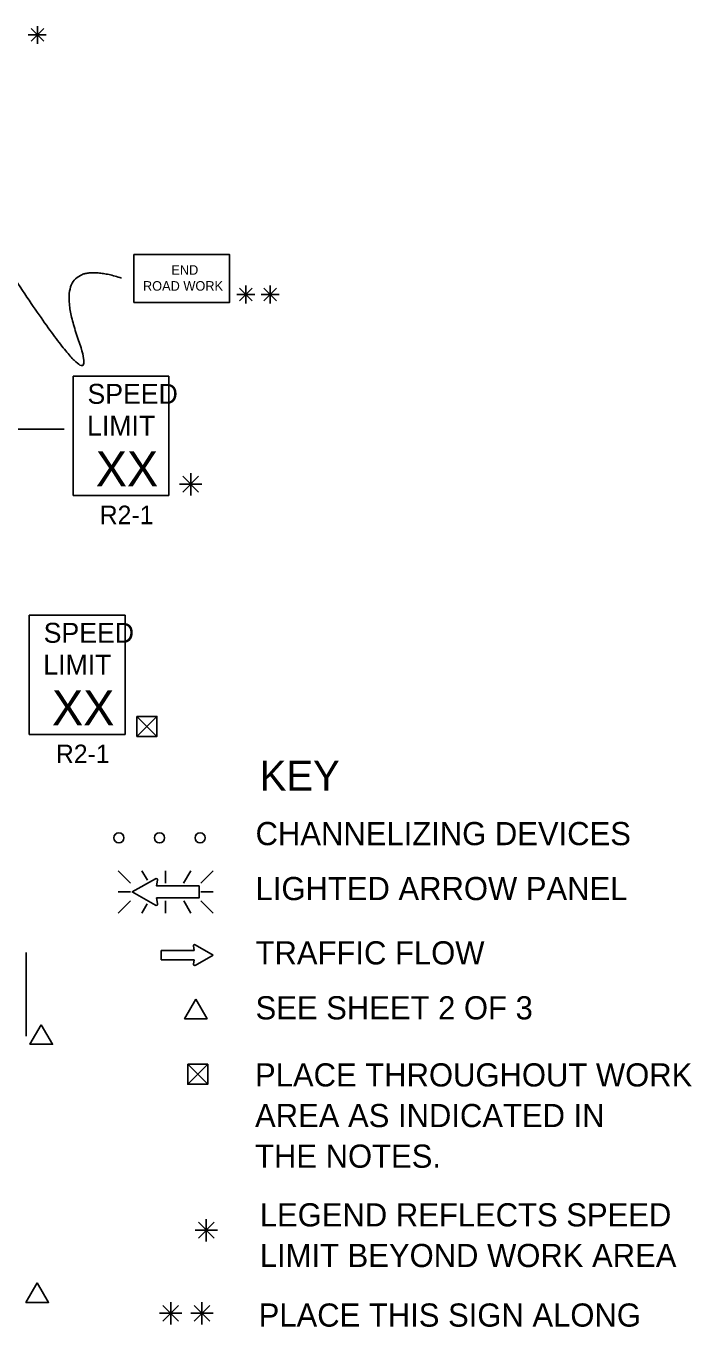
# Model space of a CAD drawing. Extents: x 16486 to 19505, y 5576 to 6998.
# Drawn here: x 17161 to 17428, y 6304 to 6826 of the extents above; entities that cross this region are included whole.
import ezdxf

# ---------------------------------------------------------------- set-up
doc = ezdxf.new("R2010")
doc.units = 0
for name, color, linetype in [('MT_SCRATCH_LEVEL_E', 7, 'Continuous'), ('TRAFFIC_SIGNS_PR', 7, 'Continuous'), ('TYPICAL_TEXT_DIMEN_EX', 7, 'Continuous'), ('TYPICAL_TEXT_DIMEN_PR', 7, 'Continuous')]:
    doc.layers.add(name, color=color, linetype=linetype)

msp = doc.modelspace()

# ---------------------------------------------------------------- linework, layer by layer
at = {"layer": 'MT_SCRATCH_LEVEL_E'}
for p, q in [((17227.72, 6457.25), (17228.03, 6455.48)), ((17235.64, 6453.62), (17228.4, 6457.73)), ((17228.03, 6455.48), (17214.78, 6455.48)), ((17214.78, 6455.48), (17214.78, 6451.73)), ((17228.4, 6449.48), (17235.64, 6453.62)), ((17214.78, 6451.73), (17228.03, 6451.73)), ((17228.03, 6451.73), (17227.72, 6449.95))]:
    msp.add_line(p, q, dxfattribs=at)
for centre, start, end in [((17228.18, 6457.33), 60.4248, 189.9638), ((17228.18, 6449.89), 170.0362, 299.7731)]:
    msp.add_arc(centre, 0.463, start, end, dxfattribs=at)
at = {"layer": 'TRAFFIC_SIGNS_PR'}
for p, q in [((17179.45, 6685.93), (17217.85, 6685.93)), ((17179.45, 6637.93), (17179.45, 6685.93)), ((17217.85, 6637.93), (17217.85, 6685.93)), ((17179.45, 6637.93), (17217.85, 6637.93)), ((17161.88, 6590.04), (17200.28, 6590.04)), ((17161.88, 6542.04), (17161.88, 6590.04)), ((17200.28, 6542.04), (17200.28, 6590.04)), ((17161.88, 6542.04), (17200.28, 6542.04)), ((17197.49, 6487.43), (17202.43, 6482.5)), ((17209.26, 6483.61), (17207.05, 6487.44)), ((17216.58, 6482.5), (17216.58, 6487.44)), ((17223.81, 6482.5), (17226.66, 6487.44)), ((17230.72, 6482.5), (17235.66, 6487.44)), ((17202.43, 6478.94), (17197.49, 6478.94)), ((17230.72, 6478.94), (17235.66, 6478.94)), ((17197.49, 6470.46), (17202.43, 6475.39)), ((17207, 6470.45), (17209.12, 6474.12)), ((17216.58, 6475.39), (17216.58, 6470.45)), ((17226.7, 6470.45), (17223.85, 6475.39)), ((17230.72, 6475.39), (17235.66, 6470.45)), ((17160.55, 6454.67), (17160.55, 6421.07))]:
    msp.add_line(p, q, dxfattribs=at)
msp.add_lwpolyline([(17203.87, 6715.44), (17242.27, 6715.44), (17242.27, 6734.64), (17203.87, 6734.64)], close=True, dxfattribs=at)
for points in [[(17212.5, 6484.22), (17203.21, 6478.94), (17212.51, 6473.62)], [(17213.38, 6474.25), (17212.98, 6476.52), (17229.99, 6476.52), (17229.99, 6481.32), (17212.98, 6481.32), (17213.38, 6483.6)]]:
    msp.add_lwpolyline(points, dxfattribs=at)
for centre in [(17197.83, 6500.63), (17214.13, 6500.63), (17230.43, 6500.63)]:
    msp.add_circle(centre, 2, dxfattribs=at)
for centre, radius, start, end in [((17212.79, 6483.7), 0.598, 350.7308, 118.8916), ((17212.79, 6474.15), 0.597, 241.4833, 9.9593)]:
    msp.add_arc(centre, radius, start, end, dxfattribs=at)
at = {"layer": 'TYPICAL_TEXT_DIMEN_PR'}
for p, q in [((17165.11, 6822.8), (17161.48, 6822.8)), ((17162.56, 6825.36), (17167.66, 6820.25)), ((17167.66, 6825.36), (17162.56, 6820.25)), ((17165.11, 6822.8), (17165.11, 6826.37)), ((17165.11, 6822.8), (17167.66, 6822.8)), ((17165.11, 6822.8), (17168.69, 6822.8)), ((17165.11, 6822.8), (17165.11, 6819.2)), ((17248.82, 6718.65), (17245.19, 6718.65)), ((17246.27, 6721.2), (17251.37, 6716.1)), ((17251.37, 6721.2), (17246.27, 6716.1)), ((17248.82, 6718.65), (17248.82, 6722.21)), ((17248.82, 6718.65), (17251.37, 6718.65)), ((17248.82, 6718.65), (17252.4, 6718.65)), ((17248.82, 6718.65), (17248.82, 6715.05)), ((17258.57, 6718.65), (17254.94, 6718.65)), ((17261.12, 6721.2), (17256.01, 6716.1)), ((17256.02, 6721.2), (17261.12, 6716.1)), ((17258.57, 6718.65), (17258.57, 6722.21)), ((17258.57, 6718.65), (17261.12, 6718.65)), ((17258.57, 6718.65), (17262.15, 6718.65)), ((17258.57, 6718.65), (17258.57, 6715.05)), ((17142.7, 6664.64), (17175.9, 6664.64)), ((17142.7, 6664.64), (17175.9, 6664.64)), ((17142.7, 6664.64), (17175.9, 6664.64)), ((17223.45, 6645.73), (17229.83, 6639.36)), ((17229.83, 6645.73), (17223.45, 6639.36)), ((17226.64, 6642.55), (17226.64, 6647)), ((17226.64, 6642.55), (17222.11, 6642.55)), ((17226.64, 6642.55), (17229.83, 6642.55)), ((17226.64, 6642.55), (17231.12, 6642.55)), ((17226.64, 6642.55), (17226.64, 6638.05)), ((17205.07, 6549.36), (17213.07, 6541.36)), ((17205.07, 6541.36), (17213.07, 6549.36)), ((17225.49, 6409.76), (17233.49, 6401.76)), ((17225.49, 6401.76), (17233.49, 6409.76)), ((17232.92, 6343.19), (17232.92, 6347.64)), ((17232.92, 6343.19), (17228.38, 6343.19)), ((17229.73, 6346.37), (17236.1, 6340)), ((17236.1, 6346.37), (17229.73, 6340)), ((17232.92, 6343.19), (17236.1, 6343.19)), ((17232.92, 6343.19), (17237.39, 6343.19)), ((17232.92, 6343.19), (17232.92, 6338.69)), ((17215.44, 6313.03), (17221.81, 6306.66)), ((17221.81, 6313.03), (17215.44, 6306.66)), ((17218.63, 6309.85), (17218.63, 6314.3)), ((17234.37, 6313.03), (17227.99, 6306.66)), ((17228, 6313.03), (17234.37, 6306.66)), ((17231.18, 6309.85), (17231.18, 6314.3)), ((17218.63, 6309.85), (17214.1, 6309.85)), ((17218.63, 6309.85), (17221.81, 6309.85)), ((17218.63, 6309.85), (17223.1, 6309.85)), ((17218.63, 6309.85), (17218.63, 6305.35)), ((17231.18, 6309.85), (17226.65, 6309.85)), ((17231.18, 6309.85), (17234.37, 6309.85)), ((17231.18, 6309.85), (17235.66, 6309.85)), ((17231.18, 6309.85), (17231.18, 6305.35))]:
    msp.add_line(p, q, dxfattribs=at)
for points in [[(17205.07, 6549.36), (17205.07, 6541.36), (17213.07, 6541.36), (17213.07, 6549.36)], [(17228.71, 6435.91), (17224.18, 6428.08), (17233.23, 6428.08)], [(17166.67, 6425.66), (17162.15, 6417.82), (17171.2, 6417.82)], [(17225.49, 6409.76), (17225.49, 6401.76), (17233.49, 6401.76), (17233.49, 6409.76)], [(17165.05, 6322.07), (17160.53, 6314.24), (17169.58, 6314.24)]]:
    msp.add_lwpolyline(points, close=True, dxfattribs=at)
msp.add_open_spline([(17154.48, 6727.28), (17192.72, 6669.11), (17169.5, 6734.81), (17198.86, 6725.23)], degree=2, dxfattribs=at)

# ---------------------------------------------------------------- texts
at = {"layer": 'TRAFFIC_SIGNS_PR'}
for s, height, p in [('END', 3.831, (17218.87, 6726.57)), ('ROAD WORK', 3.831, (17207.48, 6720.18)), ('SPEED', 8, (17185.22, 6674.79)), ('LIMIT', 8, (17185.06, 6661.99)), ('XX', 14.031, (17188.56, 6641.69)), ('R2-1', 7.44, (17190.13, 6626.49)), ('SPEED', 8, (17167.64, 6578.9)), ('LIMIT', 8, (17167.48, 6566.1)), ('XX', 14.031, (17170.99, 6545.8)), ('R2-1', 7.44, (17172.55, 6530.6))]:
    msp.add_text(s, height=height, dxfattribs=at).set_placement(p)
at = {"layer": 'TYPICAL_TEXT_DIMEN_EX'}
for s, height, p in [('KEY', 12, (17254.34, 6519.6)), ('CHANNELIZING DEVICES', 9.3, (17252.68, 6497.69)), ('LIGHTED ARROW PANEL', 9.3, (17252.68, 6475.64)), ('TRAFFIC FLOW', 9.3, (17252.68, 6449.84)), ('SEE SHEET 2 OF 3', 9.3, (17252.68, 6427.79)), ('PLACE THROUGHOUT WORK', 9.3, (17252.47, 6400.87)), ('AREA AS INDICATED IN', 9.3, (17252.47, 6384.57)), ('THE NOTES.', 9.3, (17252.47, 6368.27)), ('LEGEND REFLECTS SPEED', 9.3, (17254.37, 6344.72)), ('LIMIT BEYOND WORK AREA', 9.3, (17254.37, 6328.42)), ('PLACE THIS SIGN ALONG', 9.3, (17253.92, 6304.51))]:
    msp.add_text(s, height=height, dxfattribs=at).set_placement(p)

doc.saveas('drawing.dxf')
